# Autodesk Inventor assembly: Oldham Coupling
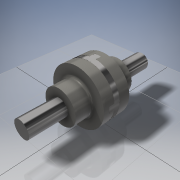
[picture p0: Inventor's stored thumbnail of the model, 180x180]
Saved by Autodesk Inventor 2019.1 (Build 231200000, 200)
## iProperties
Created: 2020-03
Part Number: Oldham Coupling
Document SubType Name: Assembly
Designer: Oghenemarho
Author: Oghenemarho
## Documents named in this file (3)
- C:\Users\Oghenemarho\Documents\Inventor\Oldham Coupling\Oldham Coupling.iam
- C:\Users\Oghenemarho\Documents\Inventor\Oldham Coupling\Disc.ipt
- C:\Users\Oghenemarho\Documents\Inventor\Oldham Coupling\Flange_subassembly.iam
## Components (3 placed, 2 different names)
1. Disc:1 — Insert:1, Mate:1, Insert:2, Mate:2
2. Flange_subassembly:1 [sub-assembly] — Insert:1, Mate:1
3. Flange_subassembly:2 [sub-assembly] — Insert:2, Mate:2
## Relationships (4: Insert 2, Mate 2)
- Insert:1: Disc:1 ↔ Flange_subassembly:1
- Mate:1: Disc:1 ↔ Flange_subassembly:1
- Insert:2: Disc:1 ↔ Flange_subassembly:2
- Mate:2: Disc:1 ↔ Flange_subassembly:2
